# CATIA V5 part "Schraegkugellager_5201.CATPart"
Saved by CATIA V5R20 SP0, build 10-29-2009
Part number: Schraegkugellager_5201
Bounding box of the stored display mesh (mm): x -16 to 16, y -16 to 16, z -7.95 to 7.95
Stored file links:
  C:\Users\Andi\Desktop\Offene Projekte\Plasmacutter\Z-Achse\Schraegkugellager_5201.CATPart
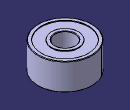
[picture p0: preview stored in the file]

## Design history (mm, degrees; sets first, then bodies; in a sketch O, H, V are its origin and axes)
AxisSystem1: origin (0, 0, 0), X (1, 0, 0), Y (0, 1, 0), Z (0, 0, 1)
Body1 (main body)
  Sketch1 on YZ plane of AxisSystem1, origin (0, 0, 0), H (0, 1, 0), V (0, 0, 1)
    line L1 (6, -7.95) -> (6, 7.95)
    line L2 (6, 7.95) -> (8, 7.95)
    line L3 (8, 7.95) -> (8, 7.45)
    line L4 (8, 7.45) -> (14, 7.45)
    line L5 (14, 7.45) -> (14, 7.95)
    point P6 (14, 7.95)
    line L6 (14, 7.95) -> (16, 7.95)
    line L7 (16, 7.95) -> (16, -7.95)
    line L8 (16, -7.95) -> (14, -7.95)
    point P9 (14, -7.95)
    line L9 (14, -7.95) -> (14, -7.45)
    line L10 (14, -7.45) -> (8, -7.45)
    point P11 (8, -7.45)
    line L11 (8, -7.45) -> (8, -7.95)
    point P12 (8, -7.95)
    line L12 (8, -7.95) -> (6, -7.95)
    reference projected line E1 through (0, 0) direction (0, 1) from edge [ZX plane of AxisSystem1 | YZ plane of AxisSystem1]
    construction line L13 (11, 7.45) -> (11, -7.45)
    point P13 (11, 7.45)
    point P14 (11, -7.45)
    distance L1 V = 6
    distance L7 E1 = 16
    length L7 = 15.9
    distance L4 L6 = 0.5
    distance L3 L1 = 2
    vertical: L1 V, L3 V, L5 V, L7 V, L9 V, L11 V, L13 V
    horizontal: L2 H, L4 H, L6 H, L8 H, L10 H, L12 H
    coincidence: P6 L2, P9 L5, P11 L3, P12 L8
    symmetry: L8 L6 H, L10 L4 H, L3 L5 L13, L1 L7 L13
    midpoint: P13 L4, P14 L10
  Shaft1: profile Sketch1, axis Sketch1.V, angle 360
  Chamfer1: length 0.3, angle 45, on edge [face of Shaft1 from Sketch1.L7 | face of Shaft1 from Sketch1.L6]; edge [face of Shaft1 from Sketch1.L8 | face of Shaft1 from Sketch1.L7]; edge [face of Shaft1 from Sketch1.L2 | face of Shaft1 from Sketch1.L1]; edge [face of Shaft1 from Sketch1.L1 | face of Shaft1 from Sketch1.L12]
